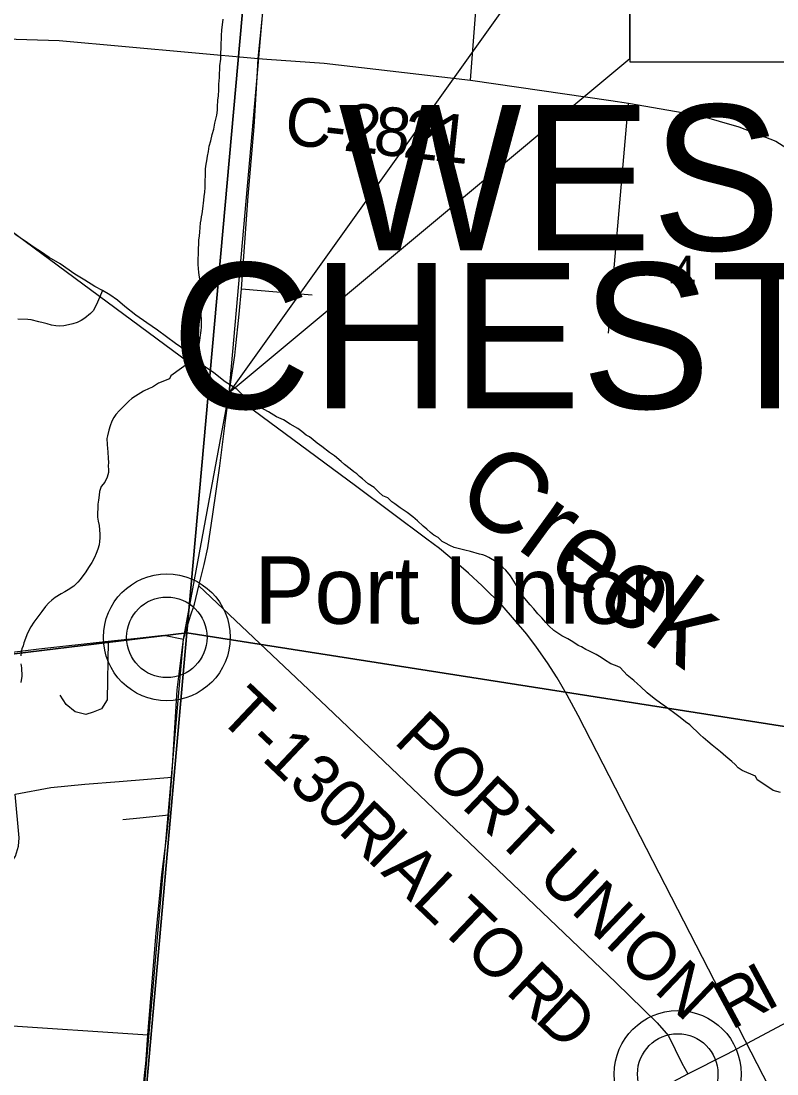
# Model space of a CAD drawing. Extents: x 0 to 34, y 0 to 22.
# Drawn here: x 4.396 to 5.283, y 16.973 to 18.207 of the extents above; entities that cross this region are included whole.
import ezdxf

# ---------------------------------------------------------------- set-up
doc = ezdxf.new("R2010")
doc.units = 0
for name, color, linetype in [('GM_X_City_Street', 7, 'Continuous'), ('GM_X_County_Road', 7, 'Continuous'), ('GM_X_County_Road_Text', 7, 'Continuous'), ('GM_X_Minor_River', 7, 'Continuous'), ('GM_X_Minor_River_Text', 7, 'Continuous'), ('GM_X_Rail_Line', 7, 'Continuous'), ('GM_X_Section', 7, 'Continuous'), ('GM_X_Section_Text', 7, 'Continuous'), ('GM_X_State_Location', 7, 'Continuous'), ('GM_X_State_Route', 7, 'Continuous'), ('GM_X_Township_Road', 7, 'Continuous'), ('GM_X_Township_Road_Text', 7, 'Continuous'), ('GM_X_Township_Text', 7, 'Continuous'), ('GM_X_Unincorporated', 7, 'Continuous'), ('GM_X_Unincorporated_Location', 7, 'Continuous'), ('GM_X_Unincorporated_Text', 7, 'Continuous'), ('SH_Text', 7, 'Continuous')]:
    doc.layers.add(name, color=color, linetype=linetype)

msp = doc.modelspace()

# ---------------------------------------------------------------- linework, layer by layer
at = {"layer": 'GM_X_City_Street'}
msp.add_lwpolyline([(4.5698, 17.2761), (4.5358, 17.2727), (4.5156, 17.2705)], dxfattribs=at)
at = {"layer": 'GM_X_County_Road'}
for points in [[(3.627, 18.1271), (3.7655, 18.0478), (3.8255, 18.0096), (3.8854, 17.9841), (3.9304, 17.9759), (3.9821, 17.9774), (4.0423, 17.9922), (4.0862, 18.0148), (4.1461, 18.0623), (4.223, 18.1271), (4.2464, 18.1466), (4.2759, 18.167), (4.3203, 18.183), (4.3649, 18.1867), (4.441, 18.1842), (4.6746, 18.1631), (4.6846, 18.1624)], [(4.6846, 18.1624), (4.7517, 18.1578), (4.9233, 18.1379), (5.0879, 18.1139), (5.1086, 18.1108), (5.192, 18.0966), (5.238, 18.0831), (5.2814, 18.0662), (5.3381, 18.0304), (5.3678, 18.0072), (5.4117, 17.9578), (5.4392, 17.9278), (5.4607, 17.9078), (5.5032, 17.8793), (5.5302, 17.8663), (5.5602, 17.8558), (5.6163, 17.8474)], [(3.5629, 17.3674), (3.5638, 17.3673), (3.5831, 17.367), (3.6256, 17.3718), (3.6484, 17.3765), (3.8461, 17.4003), (4.0282, 17.423), (4.2903, 17.4561), (4.3826, 17.4667), (4.417, 17.4713), (4.4983, 17.48), (4.5325, 17.4838), (4.5638, 17.487), (4.5869, 17.4825)]]:
    msp.add_lwpolyline(points, dxfattribs=at)
at = {"layer": 'GM_X_Minor_River'}
for points in [[(4.6296, 18.1545), (4.6305, 18.1624), (4.6306, 18.1681), (4.6312, 18.1769), (4.6314, 18.1902), (4.6319, 18.1963), (4.6334, 18.2095)], [(4.5996, 17.811), (4.6052, 17.8279), (4.606, 17.8328), (4.6069, 17.8389), (4.6074, 17.8442), (4.6078, 17.8484), (4.608, 17.8575), (4.6077, 17.8621), (4.6079, 17.8682), (4.6084, 17.8735), (4.6081, 17.8792), (4.608, 17.8929), (4.6074, 17.8986), (4.6056, 17.907), (4.605, 17.9123), (4.604, 17.9219), (4.6044, 17.9405), (4.6049, 17.9454), (4.605, 17.9504), (4.6055, 17.9553), (4.6059, 17.9595), (4.6069, 17.9705), (4.6074, 17.9739), (4.6078, 17.9777), (4.6087, 17.9811), (4.6095, 17.9868), (4.6105, 17.997), (4.611, 18.0016), (4.6118, 18.0065), (4.6123, 18.0118), (4.6128, 18.0339), (4.6136, 18.0392), (4.6141, 18.0434), (4.6149, 18.0487), (4.6162, 18.0543), (4.6171, 18.0604), (4.6187, 18.0668), (4.6204, 18.074), (4.6224, 18.0805), (4.6237, 18.0873), (4.6258, 18.0967), (4.6266, 18.1028), (4.6267, 18.1066), (4.6272, 18.1142), (4.6277, 18.1195), (4.6283, 18.1264), (4.6284, 18.1332), (4.6289, 18.1408), (4.629, 18.1454), (4.6295, 18.1507), (4.6296, 18.1545)], [(4.6639, 17.7611), (4.6495, 17.7756), (4.6357, 17.784), (4.6223, 17.7947), (4.6127, 17.8014), (4.5996, 17.811), (4.59, 17.8204), (4.5774, 17.8291), (4.567, 17.8371), (4.5565, 17.8446), (4.5439, 17.8533), (4.5308, 17.8625), (4.5182, 17.8724), (4.5093, 17.8799), (4.5004, 17.8862), (4.4918, 17.8914), (4.4828, 17.8959), (4.4712, 17.9035), (4.4593, 17.9103), (4.4421, 17.9226), (4.4294, 17.9298), (4.4201, 17.9362), (4.4104, 17.9426), (4.4011, 17.9489), (4.3896, 17.9569)], [(4.4918, 17.8914), (4.486, 17.8775), (4.4832, 17.8715), (4.4808, 17.8674), (4.4777, 17.8641), (4.471, 17.8586), (4.4668, 17.8561), (4.4622, 17.8539), (4.4572, 17.8522), (4.4518, 17.8508), (4.4465, 17.8499), (4.4415, 17.8493), (4.437, 17.8498), (4.432, 17.8507), (4.4268, 17.852), (4.4222, 17.8533), (4.417, 17.8546), (4.4083, 17.8567), (4.4041, 17.8572), (4.3927, 17.8576)], [(4.5996, 17.811), (4.5721, 17.7913), (4.5704, 17.7875), (4.5574, 17.7826), (4.5504, 17.7779), (4.5466, 17.7765), (4.54, 17.7733), (4.5307, 17.7675), (4.5264, 17.7646), (4.5229, 17.7616), (4.5155, 17.7546), (4.5116, 17.7506), (4.5073, 17.7458), (4.5053, 17.7424), (4.5028, 17.7379), (4.5008, 17.7326), (4.4991, 17.7274), (4.4978, 17.721), (4.4969, 17.7176), (4.4975, 17.7107), (4.4977, 17.7061), (4.498, 17.7019), (4.4985, 17.6943), (4.4988, 17.6898), (4.4986, 17.6852), (4.4989, 17.6814), (4.4988, 17.678), (4.4975, 17.6723), (4.4947, 17.6667), (4.4903, 17.6615), (4.4883, 17.6555), (4.4881, 17.6513), (4.4872, 17.6456), (4.4863, 17.6407), (4.4859, 17.6255), (4.4869, 17.6209), (4.4878, 17.6156), (4.4885, 17.6106), (4.4887, 17.6057), (4.4886, 17.6011), (4.4884, 17.5969), (4.4879, 17.5932), (4.4863, 17.5879), (4.4846, 17.583), (4.4826, 17.5781), (4.4794, 17.5725), (4.4754, 17.5665), (4.4722, 17.5613), (4.4658, 17.5524), (4.4631, 17.5491), (4.4584, 17.5446), (4.4514, 17.5403), (4.4476, 17.5381), (4.4433, 17.5356), (4.4363, 17.5312), (4.4324, 17.5283), (4.4289, 17.525), (4.425, 17.5206), (4.4207, 17.515), (4.4112, 17.5024), (4.4076, 17.4968), (4.4047, 17.4912), (4.4031, 17.4874), (4.4015, 17.4833), (4.3994, 17.478), (4.3986, 17.4746), (4.3973, 17.4712), (4.3964, 17.4671), (4.3959, 17.4629)], [(5.2166, 17.3504), (5.207, 17.3582), (5.2018, 17.3625), (5.1962, 17.3672), (5.1929, 17.3703), (5.1888, 17.3742), (5.1843, 17.3785), (5.1806, 17.382), (5.1758, 17.3855), (5.1694, 17.3906), (5.1631, 17.3953), (5.1557, 17.4008), (5.1512, 17.4039), (5.1463, 17.4074), (5.1404, 17.4117), (5.137, 17.4145), (5.1307, 17.4195), (5.1229, 17.4269), (5.1192, 17.43), (5.1151, 17.4339), (5.111, 17.4371), (5.1073, 17.4402), (5.0988, 17.4491), (5.0935, 17.4515), (5.0879, 17.4535), (5.0808, 17.4582), (5.0767, 17.461), (5.0707, 17.4645), (5.067, 17.4665), (5.0621, 17.4689), (5.0588, 17.4705), (5.0535, 17.4736), (5.0498, 17.4752), (5.0435, 17.4795), (5.0375, 17.4827), (5.0304, 17.4863), (5.0259, 17.4894), (5.021, 17.4926), (5.0155, 17.498), (5.0118, 17.5019), (5.007, 17.5073), (5.0025, 17.5123), (4.9977, 17.5181), (4.9933, 17.5228), (4.9892, 17.5278), (4.9855, 17.5321), (4.9826, 17.5363), (4.9786, 17.5436), (4.9764, 17.5475), (4.9705, 17.5567), (4.965, 17.5633), (4.9613, 17.5664), (4.9535, 17.5731), (4.9449, 17.5782), (4.9411, 17.5802), (4.9378, 17.5814), (4.934, 17.5822), (4.9235, 17.5851), (4.9167, 17.5868), (4.9107, 17.5884), (4.9043, 17.5901), (4.8991, 17.5924), (4.8942, 17.5948), (4.8901, 17.5968), (4.8856, 17.6015), (4.8804, 17.6042), (4.8767, 17.6074), (4.8722, 17.6113), (4.8681, 17.6148), (4.8614, 17.621), (4.8559, 17.6257), (4.8492, 17.6311), (4.841, 17.6366), (4.8346, 17.641), (4.8313, 17.6433), (4.8265, 17.648), (4.8208, 17.6504), (4.816, 17.6546), (4.8104, 17.6601), (4.8033, 17.6644), (4.7967, 17.6703), (4.7933, 17.673), (4.79, 17.6761), (4.7866, 17.6788), (4.7825, 17.682), (4.7758, 17.6871), (4.7717, 17.6906), (4.7639, 17.6972), (4.758, 17.7011), (4.749, 17.7085), (4.7438, 17.7124), (4.739, 17.7163), (4.7345, 17.7195), (4.7308, 17.7218), (4.7256, 17.7261), (4.7211, 17.7293), (4.7118, 17.7344), (4.7043, 17.7395), (4.6961, 17.7431), (4.6867, 17.749), (4.6639, 17.7611)], [(4.396, 17.4534), (4.3967, 17.4488), (4.3971, 17.4389), (4.3962, 17.4317)], [(5.2871, 17.3026), (5.2785, 17.305), (5.2688, 17.3117), (5.2598, 17.3176), (5.2577, 17.3218), (5.2419, 17.3286), (5.2374, 17.3317), (5.2337, 17.3356), (5.23, 17.3391), (5.223, 17.345), (5.2166, 17.3504)]]:
    msp.add_lwpolyline(points, dxfattribs=at)
at = {"layer": 'GM_X_Rail_Line'}
msp.add_lwpolyline([(5.5527, 16.4145), (5.3725, 16.7649), (5.3098, 16.8872), (5.1812, 17.1373), (5.0499, 17.393), (5.037, 17.4166), (5.0252, 17.437), (5.0139, 17.4546), (5.001, 17.4731), (4.9895, 17.4883), (4.9752, 17.5053), (4.9605, 17.5218), (4.9371, 17.5451), (4.921, 17.5598), (4.9044, 17.5741), (4.8871, 17.5886), (4.8723, 17.5997), (4.7884, 17.6623), (4.6417, 17.7708), (4.3528, 17.9844), (3.8782, 18.3346)], dxfattribs=at)
at = {"layer": 'GM_X_Section'}
for points in [[(4.6831, 18.5192), (4.5906, 17.4897), (3.5572, 17.3639), (3.6423, 18.3609)], [(3.5572, 17.3639), (4.5906, 17.4897), (4.4981, 16.447), (3.4704, 16.3589)]]:
    msp.add_lwpolyline(points, close=True, dxfattribs=at)
for points in [[(5.6474, 18.1592), (5.5736, 17.336), (4.5906, 17.4897), (4.6831, 18.5192), (5.1102, 18.4472)], [(4.8773, 16.3947), (4.4981, 16.447), (4.5906, 17.4897), (5.5736, 17.336), (5.489, 16.4145)]]:
    msp.add_lwpolyline(points, dxfattribs=at)
at = {"layer": 'GM_X_State_Route'}
for points in [[(4.6479, 17.823), (4.6523, 17.8636), (4.6547, 17.8932), (4.6627, 18.002), (4.6698, 18.083), (4.6732, 18.1415), (4.6746, 18.1631), (4.6817, 18.2366), (4.6849, 18.2753)], [(4.5459, 17.0281), (4.5497, 17.0757), (4.5545, 17.1336), (4.5616, 17.2066), (4.5673, 17.2521), (4.5698, 17.2761), (4.5731, 17.3208), (4.5796, 17.4231), (4.5869, 17.4825), (4.5947, 17.5088), (4.5997, 17.5236), (4.605, 17.5449), (4.6112, 17.57), (4.6154, 17.5895), (4.6213, 17.6291), (4.6296, 17.6856), (4.6361, 17.7388), (4.6405, 17.7714), (4.647, 17.8151), (4.6479, 17.823)], [(4.543, 16.9897), (4.5451, 17.0182), (4.5459, 17.0281)], [(4.5342, 16.8956), (4.5364, 16.9219), (4.5409, 16.9707), (4.5426, 16.9849), (4.543, 16.9897)]]:
    msp.add_lwpolyline(points, dxfattribs=at)
at = {"layer": 'GM_X_Township_Road'}
for p, q in [((4.9233, 18.1379), (4.9365, 18.304)), ((5.0852, 17.8411), (5.1086, 18.1108)), ((4.6547, 17.8932), (4.7378, 17.8863)), ((4.5451, 17.0182), (4.3312, 17.0322))]:
    msp.add_line(p, q, dxfattribs=at)
for points in [[(4.605, 17.5449), (4.7549, 17.403), (4.9554, 17.212), (5.0939, 17.08), (5.1424, 17.0327), (5.1555, 17.0175), (5.1715, 16.9852), (5.1782, 16.9728)], [(4.4983, 17.48), (4.4973, 17.4114), (4.4906, 17.4008), (4.4809, 17.3969), (4.4724, 17.3942), (4.4597, 17.3972), (4.4491, 17.406), (4.4422, 17.4166)], [(4.379, 17.2115), (4.3898, 17.2282), (4.3934, 17.2397), (4.394, 17.2497), (4.3895, 17.3009), (4.4313, 17.3085), (4.4712, 17.3124), (4.5115, 17.3157), (4.5731, 17.3208)], [(5.1782, 16.9728), (5.2241, 16.9957), (5.3665, 17.0716), (5.4316, 17.1072), (5.5229, 17.1614), (5.5369, 17.1739), (5.5533, 17.1982), (5.5614, 17.2271), (5.5641, 17.262), (5.5717, 17.3314)], [(4.5335, 16.8862), (4.6547, 16.8768), (4.7622, 16.8695), (5.0586, 16.8468), (5.0851, 16.8444), (5.0924, 16.8449), (5.0979, 16.8513), (5.1007, 16.8591), (5.0997, 16.8683), (5.1025, 16.8743), (5.1097, 16.8757), (5.1191, 16.8735), (5.1307, 16.8749), (5.1349, 16.8851), (5.1343, 16.8969), (5.1379, 16.94), (5.1449, 16.955), (5.1782, 16.9728)]]:
    msp.add_lwpolyline(points, dxfattribs=at)
at = {"layer": 'GM_X_Unincorporated'}
for centre, radius in [((4.5673, 17.4846), 0.0744), ((4.5673, 17.4846), 0.0472), ((5.1665, 16.9726), 0.0744), ((5.1665, 16.9726), 0.0472)]:
    msp.add_circle(centre, radius, dxfattribs=at)
at = {"layer": 'GM_X_Unincorporated_Location'}
msp.add_line((4.5673, 17.4846), (4.5673, 17.4846), dxfattribs=at)
at = {"layer": 'SH_Text'}
for points in [[(8.8041, 18.7255), (5.1102, 18.7255), (5.1102, 18.1592), (8.8041, 18.1592)], [(5.1102, 18.4296), (4.6405, 17.7717), (5.1102, 18.1632)]]:
    msp.add_lwpolyline(points, close=True, dxfattribs=at)
msp.add_lwpolyline([(4.4077, 15.4283), (4.5869, 17.4825), (4.6405, 17.7714), (4.6732, 18.1415), (4.69, 18.3364), (4.6901, 18.5827)], dxfattribs=at)

# ---------------------------------------------------------------- texts
at = {"layer": 'GM_X_County_Road_Text'}
for s, rotation, p in [('C', 353.6702, (4.7037, 18.0631)), ('2', 353.6746, (4.7733, 18.0554)), ('8', 353.6928, (4.8081, 18.0515)), ('2', 353.7588, (4.8429, 18.0477)), ('1', 353.9991, (4.878, 18.0438)), ('-', 353.6684, (4.7501, 18.0579))]:
    msp.add_text(s, height=0.0568, rotation=rotation, dxfattribs=at).set_placement(p)
at = {"layer": 'GM_X_Minor_River_Text'}
msp.add_text('Creek', height=0.0947, rotation=324.0162, dxfattribs=at).set_placement((4.9013, 17.6439))
at = {"layer": 'GM_X_Section_Text'}
msp.add_text('4', height=0.0419, rotation=0, dxfattribs=at).set_placement((5.157, 17.8901))
at = {"layer": 'GM_X_State_Location'}
for s in ['s', 'r']:
    msp.add_text(s, height=0.000189, dxfattribs=at).set_placement((4.5535, 17.0896))
msp.add_text('747', height=0.000189, rotation=0, dxfattribs=at).set_placement((4.4866, 17.0759))
at = {"layer": 'GM_X_Township_Road_Text'}
for s, height, rotation, p in [('T-130', 0.05682, 316.5908, (4.6251, 17.391)), ('PORT UNION', 0.05682, 316.2871, (4.8321, 17.3617)), ('R', 0.0568, 316.2227, (4.7667, 17.2568)), ('I', 0.0568, 316.2199, (4.8003, 17.2245)), ('A', 0.0568, 316.2244, (4.8172, 17.2084)), ('L', 0.0568, 316.2213, (4.8533, 17.1738)), ('T', 0.0568, 316.2245, (4.884, 17.1444)), ('O', 0.0568, 316.2236, (4.9147, 17.115)), ('R', 0.0568, 316.266, (4.9634, 17.0682)), ('I', 0.0568, 28.3319, (5.2704, 17.0457)), ('R', 0.0568, 28.33, (5.2293, 17.0236)), ('D', 0.0568, 316.5791, (4.9974, 17.0357))]:
    msp.add_text(s, height=height, rotation=rotation, dxfattribs=at).set_placement(p)
at = {"layer": 'GM_X_Township_Text'}
for s, p in [('WEST', (4.7686, 17.9384)), ('CHESTER', (4.572, 17.7529))]:
    msp.add_text(s, height=0.17045, rotation=0, dxfattribs=at).set_placement(p)
at = {"layer": 'GM_X_Unincorporated_Text'}
msp.add_text('Port Union', height=0.07898, rotation=0, dxfattribs=at).set_placement((4.67, 17.5005))

doc.saveas('drawing.dxf')
